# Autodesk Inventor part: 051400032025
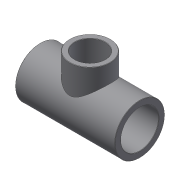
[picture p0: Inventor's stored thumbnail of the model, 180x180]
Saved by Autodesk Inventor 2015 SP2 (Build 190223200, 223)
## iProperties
Created: 2017-10
Part Number: 051400032025
Material: Generic
Description: PLASSON REDUCER TEE - CEMENT PVC 32-25-32
Document SubType Name: Modeling
Designer: KIM
Density: 1 g/cm^3
Appearance: Default
Author: KIM
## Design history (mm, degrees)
derived "051400.ipt"
feature "Solid1::051400.ipt"
feature "Solid2::051400.ipt"
tag "TaggingFeature1"
body "Solid1"
other parameters: "d0" = 78, "d1" = 41, "d2" = 22, "d4" = 32, "d5" = 28.8, "d7" = 0.32, "d8" = 22, "d9" = 36.5, "d10" = 33, "d11" = 25, "d12" = 22.5, "d23" = 19, "d24" = 0.32, "d26" = 0, "d30" = 0, "d32" = 0, "d_" = 32, "E_" = 41, "H_" = 78, "l_" = 22, "Z_" = 14, "E_1" = 33, "l_1" = 19, "Z_1" = 12.5, "H_1" = 57, "d_1" = 25
